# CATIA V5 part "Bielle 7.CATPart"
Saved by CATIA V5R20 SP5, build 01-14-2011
Part number: Bielle 7
Bounding box of the stored display mesh (mm): x -295 to -210, y -305 to -195, z -30 to 110
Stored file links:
  U:\CFAO\Thinkmotion\Bielle 7.CATPart
  U:\CFAO\Thinkmotion\Bras Articule.CATProduct
  U:\CFAO\Thinkmotion\Squelette Bielle 7.CATPart
  U:\CFAO\Thinkmotion\Bielle 8.CATPart
  U:\CFAO\Thinkmotion\Squelette Bielle 6.CATPart
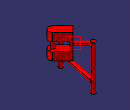
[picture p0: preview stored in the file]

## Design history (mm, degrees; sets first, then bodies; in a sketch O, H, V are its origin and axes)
Set1
  Plane1: linked copy from another document
  Point1: linked copy from another document
  Line1: linked copy from another document
  Point2: linked copy from another document
  Point3: linked copy from another document
  Plane2: linked copy from another document
  Point4: linked copy from another document
  Line2: linked copy from another document
  Line3: linked copy from another document
  Point5: linked copy from another document
Body1 (main body)
  Sketch1 on Plane1, origin (0, 0, 0), H (1, 0, 0), V (0, 1, 0)
    circle A1 centre (-270, -200) radius 5
    reference projected point E1 (-270, -200) from Point1
    radius A1 = 5
    concentricity: A1 E1
  Pad1: profile Sketch1, direction (0, 0, 1), length 25, mirrored extent
  Sketch2 on end face of Pad1, origin (0, 0, 25), H (1, 0, 0), V (0, 1, 0)
    circle A1 centre (-270, -200) radius 5
    reference projected point E1 (-270, -200) from Point1
    radius A1 = 5
    concentricity: A1 E1
  Pad2: profile Sketch2, direction (0, 0, 1), length 60
  Sketch3 on Plane2, origin (0, 0, 80), H (1, 0, 0), V (0, 1, 0)
    line L1 (-270, -200) -> (-266.4645, -196.4645)
    line L2 (-266.4645, -196.4645) -> (-241.2132, -221.7157)
    line L3 (-241.2132, -221.7157) -> (-244.7487, -225.2513)
    line L4 (-244.7487, -225.2513) -> (-270, -200)
    reference projected line E1 (-270, -200) -> (-220, -250) from Line1
    reference projected point E2 (-270, -200) from Point4
    reference projected point E3 (-220, -250) from Point3
    reference projected line E4 (-270, -200) -> (-220, -250) from Line1
    distance L3 E3 = 35
    distance L2 E4 = 5
    perpendicularity: L2 L1
    parallelism: L3 L1, L2 L4
    coincidence: L4 E1, L1 E2
  Shaft1: profile Sketch3, axis Line1, angle 360
  Plane3: type 2Lines, Element1 Line1, Element2 Line2
  Sketch4 on Plane3, origin (-235, -235, 0), H (0.7071, -0.7071, 0), V (0, 0, 1)
    line L1 (31.2132, 90) -> (31.2132, 110)
    line L2 (31.2132, 110) -> (-13.7868, 110)
    line L3 (-13.7868, 110) -> (-13.7868, 81.9743)
    point P5 (-13.7868, 68.8205)
    line L4 (-13.7868, 68.8205) -> (-13.7868, 50)
    line L5 (-13.7868, 50) -> (31.2132, 50)
    point P7 (31.2132, 50)
    line L6 (31.2132, 50) -> (31.2132, 70)
    line L7 (31.2132, 70) -> (-8.7868, 70)
    line L8 (-8.7868, 70) -> (-8.7868, 90)
    line L9 (-8.7868, 90) -> (31.2132, 90)
    line L10 (-13.7868, 81.9743) -> (-13.7868, 68.8205)
    reference projected line E1 (-13.7868, 85) -> (-13.7868, 75) from edge [face of Shaft1 from Sketch3.L2 | face of Shaft1 from Sketch3.L3]
    reference projected line E2 (-13.7868, 85) -> (-13.7868, 75) from edge [face of Shaft1 from Sketch3.L2 | face of Shaft1 from Sketch3.L3]
    reference projected line E3 (-49.4975, 80) -> (21.2132, 80) from Line1
    reference projected line E4 (-49.4975, 80) -> (21.2132, 80) from Line1
    reference projected line E5 (-49.4975, 80) -> (21.2132, 80) from Line1
    reference projected line E6 (-49.4975, 80) -> (21.2132, 80) from Line1
    distance L2 L9 = 20
    length L7 = 40
    distance L8 L10 = 5
    distance L5 L2 = 60
    perpendicularity: L2 L1
    parallelism: L3 L1, L4 L3, L6 L1, L8 L4, L10 E1, L2 E3, L9 L7, L7 E6, L4 L10, L10 L3
    coincidence: P5 L3, P7 L1, L10 E2
    vertical: L10 V
    symmetry: L5 L2 E4, L9 L7 E5
  Pad3: profile Sketch4, direction (-0.7071, -0.7071, 0), length 10, mirrored extent
  Fillet1: radius 10, on edge [face of Pad3 from Sketch4.L1 | end face of Pad3]; edge [start face of Pad3 | face of Pad3 from Sketch4.L1]; edge [face of Pad3 from Sketch4.L6 | end face of Pad3]; edge [start face of Pad3 | face of Pad3 from Sketch4.L6]
  Sketch5 on Plane1, origin (0, 0, 0), H (1, 0, 0), V (0, 1, 0)
    line L1 (-274.9029, -199.0194) -> (-294.9029, -299.0194)
    line L2 (-294.9029, -299.0194) -> (-290, -300)
    line L3 (-290, -300) -> (-270, -200)
    line L4 (-270, -200) -> (-274.9029, -199.0194)
    reference projected line E1 (-270, -200) -> (-290, -300) from Line3
    reference projected point E2 (-270, -200) from Point1
    reference projected point E3 (-290, -300) from Point5
    reference projected line E4 (-270, -200) -> (-290, -300) from Line3
    distance L1 E4 = 5
    perpendicularity: L2 L1
    parallelism: L3 L1, L4 L2
    coincidence: L3 E1, L4 E2, L2 E3
  Shaft2: profile Sketch5, axis Line3, angle 360
  Sketch6 on Plane1, origin (0, 0, 0), H (1, 0, 0), V (0, 1, 0)
    circle A1 centre (-290, -300) radius 5
    reference projected point E1 (-290, -300) from Point5
    radius A1 = 5
    concentricity: E1 A1
  Pad4: profile Sketch6, direction (0, 0, 1), length 30, mirrored extent
  Sketch7 on face of Pad3 from Sketch4.L2, origin (0, 0, 110), H (1, 0, 0), V (0, 1, 0)
    circle A1 centre (-220, -250) radius 5
    reference projected arc E1 centre (-220, -250) radius 10 from (-212.9289, -257.0711) to (-212.9289, -242.9289) ccw from edge [face of Pad3 from Sketch4.L2 | face of Fillet1]
    radius A1 = 5
    concentricity: A1 E1
  Pad5: profile Sketch7, direction (0, 0, -1), up to the existing solid (limit type 3)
